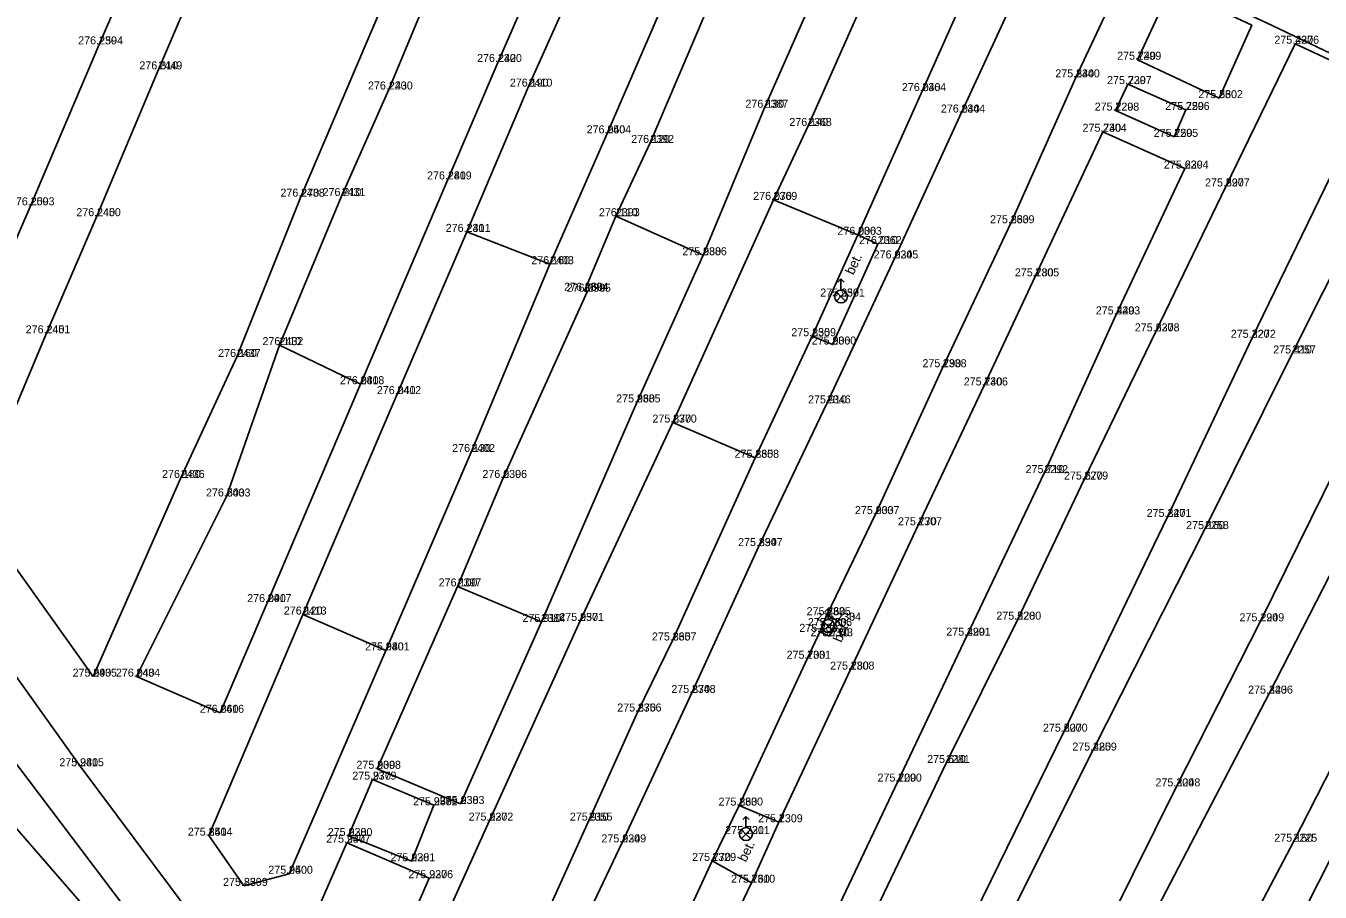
# Model space of a CAD drawing. Extents: x -776701 to -776081, y -974398 to -973771.
# Drawn here: x -776453.14 to -776412.71, y -974160.9 to -974133.83 of the extents above; entities that cross this region are included whole.
import ezdxf

# ---------------------------------------------------------------- set-up
doc = ezdxf.new("R2010")
doc.units = 0
for name, color, linetype in [('1 Body-bod', 7, 'Continuous'), ('10 Silnice-chodniky', 7, 'Continuous'), ('2 Body-cislo', 7, 'Continuous'), ('3 Body-vyska', 7, 'Continuous'), ('40 Popis-povrch', 7, 'Continuous'), ('58 Mobiliar', 7, 'Continuous'), ('7 Ploty', 7, 'Continuous'), ('Hranice parcel', 7, 'Continuous')]:
    doc.layers.add(name, color=color, linetype=linetype)

msp = doc.modelspace()

# ---------------------------------------------------------------- linework, layer by layer
at = {"layer": '1 Body-bod'}
for p, q in [((-776450.85, -974134.41), (-776450.85, -974134.41)), ((-776413.49, -974134.39), (-776413.49, -974134.39)), ((-776418.42, -974134.89), (-776418.42, -974134.89)), ((-776449, -974135.19), (-776449, -974135.19)), ((-776438.39, -974134.96), (-776438.39, -974134.96)), ((-776437.44, -974135.73), (-776437.44, -974135.73)), ((-776420.34, -974135.44), (-776420.34, -974135.44)), ((-776418.72, -974135.65), (-776418.72, -974135.65)), ((-776441.8, -974135.82), (-776441.8, -974135.82)), ((-776425.14, -974135.87), (-776425.14, -974135.87)), ((-776415.87, -974136.09), (-776415.87, -974136.09)), ((-776430.07, -974136.39), (-776430.07, -974136.39)), ((-776419.11, -974136.48), (-776419.11, -974136.48)), ((-776416.91, -974136.46), (-776416.91, -974136.46)), ((-776423.92, -974136.54), (-776423.92, -974136.54)), ((-776434.98, -974137.19), (-776434.98, -974137.19)), ((-776428.71, -974136.96), (-776428.71, -974136.96)), ((-776419.5, -974137.14), (-776419.5, -974137.14)), ((-776417.27, -974137.3), (-776417.27, -974137.3)), ((-776433.64, -974137.49), (-776433.64, -974137.49)), ((-776416.94, -974138.29), (-776416.94, -974138.29)), ((-776439.96, -974138.63), (-776439.96, -974138.63)), ((-776415.66, -974138.85), (-776415.66, -974138.85)), ((-776444.55, -974139.17), (-776444.55, -974139.17)), ((-776443.28, -974139.15), (-776443.28, -974139.15)), ((-776429.79, -974139.27), (-776429.79, -974139.27)), ((-776452.99, -974139.44), (-776452.99, -974139.44)), ((-776450.92, -974139.78), (-776450.92, -974139.78)), ((-776434.71, -974139.78), (-776434.71, -974139.78)), ((-776422.38, -974140), (-776422.38, -974140)), ((-776439.37, -974140.27), (-776439.37, -974140.27)), ((-776427.15, -974140.36), (-776427.15, -974140.36)), ((-776426.53, -974140.65), (-776426.53, -974140.65)), ((-776436.77, -974141.28), (-776436.77, -974141.28)), ((-776431.99, -974141), (-776431.99, -974141)), ((-776426.01, -974141.1), (-776426.01, -974141.1)), ((-776421.61, -974141.66), (-776421.61, -974141.66)), ((-776435.69, -974142.11), (-776435.69, -974142.11)), ((-776435.61, -974142.14), (-776435.61, -974142.14)), ((-776427.68, -974142.29), (-776427.68, -974142.29)), ((-776419.08, -974142.85), (-776419.08, -974142.85)), ((-776417.85, -974143.38), (-776417.85, -974143.38)), ((-776452.5, -974143.44), (-776452.5, -974143.44)), ((-776445.22, -974143.81), (-776445.22, -974143.81)), ((-776428.58, -974143.53), (-776428.58, -974143.53)), ((-776427.95, -974143.79), (-776427.95, -974143.79)), ((-776414.84, -974143.58), (-776414.84, -974143.58)), ((-776446.55, -974144.18), (-776446.55, -974144.18)), ((-776413.59, -974144.07), (-776413.59, -974144.07)), ((-776424.5, -974144.5), (-776424.5, -974144.5)), ((-776442.69, -974145.03), (-776442.69, -974145.03)), ((-776441.54, -974145.34), (-776441.54, -974145.34)), ((-776423.21, -974145.07), (-776423.21, -974145.07)), ((-776434.06, -974145.6), (-776434.06, -974145.6)), ((-776428.12, -974145.63), (-776428.12, -974145.63)), ((-776432.93, -974146.23), (-776432.93, -974146.23)), ((-776439.23, -974147.15), (-776439.23, -974147.15)), ((-776430.36, -974147.33), (-776430.36, -974147.33)), ((-776421.33, -974147.81), (-776421.33, -974147.81)), ((-776448.3, -974147.96), (-776448.3, -974147.96)), ((-776438.23, -974147.96), (-776438.23, -974147.96)), ((-776420.08, -974148.01), (-776420.08, -974148.01)), ((-776446.87, -974148.54), (-776446.87, -974148.54)), ((-776426.6, -974149.09), (-776426.6, -974149.09)), ((-776425.27, -974149.44), (-776425.27, -974149.44)), ((-776417.48, -974149.18), (-776417.48, -974149.18)), ((-776416.31, -974149.56), (-776416.31, -974149.56)), ((-776430.25, -974150.09), (-776430.25, -974150.09)), ((-776439.66, -974151.35), (-776439.66, -974151.35)), ((-776445.59, -974151.84), (-776445.59, -974151.84)), ((-776444.49, -974152.23), (-776444.49, -974152.23)), ((-776428.12, -974152.25), (-776428.12, -974152.25)), ((-776437.04, -974152.46), (-776437.04, -974152.46)), ((-776435.83, -974152.43), (-776435.83, -974152.43)), ((-776428.08, -974152.59), (-776428.08, -974152.59)), ((-776427.8, -974152.42), (-776427.8, -974152.42)), ((-776422.17, -974152.39), (-776422.17, -974152.39)), ((-776414.58, -974152.44), (-776414.58, -974152.44)), ((-776432.94, -974153.04), (-776432.94, -974153.04)), ((-776428.34, -974152.77), (-776428.34, -974152.77)), ((-776428.05, -974152.91), (-776428.05, -974152.91)), ((-776423.75, -974152.89), (-776423.75, -974152.89)), ((-776441.9, -974153.35), (-776441.9, -974153.35)), ((-776428.74, -974153.61), (-776428.74, -974153.61)), ((-776451.04, -974154.17), (-776451.04, -974154.17)), ((-776449.69, -974154.17), (-776449.69, -974154.17)), ((-776427.38, -974153.95), (-776427.38, -974153.95)), ((-776432.34, -974154.68), (-776432.34, -974154.68)), ((-776414.31, -974154.7), (-776414.31, -974154.7)), ((-776447.07, -974155.3), (-776447.07, -974155.3)), ((-776434.03, -974155.26), (-776434.03, -974155.26)), ((-776420.72, -974155.89), (-776420.72, -974155.89)), ((-776419.81, -974156.48), (-776419.81, -974156.48)), ((-776451.45, -974156.97), (-776451.45, -974156.97)), ((-776442.17, -974157.05), (-776442.17, -974157.05)), ((-776424.4, -974156.87), (-776424.4, -974156.87)), ((-776442.31, -974157.39), (-776442.31, -974157.39)), ((-776425.9, -974157.45), (-776425.9, -974157.45)), ((-776417.2, -974157.6), (-776417.2, -974157.6)), ((-776440.4, -974158.19), (-776440.4, -974158.19)), ((-776439.56, -974158.15), (-776439.56, -974158.15)), ((-776430.86, -974158.2), (-776430.86, -974158.2)), ((-776438.66, -974158.67), (-776438.66, -974158.67)), ((-776435.56, -974158.67), (-776435.56, -974158.67)), ((-776429.62, -974158.72), (-776429.62, -974158.72)), ((-776447.43, -974159.14), (-776447.43, -974159.14)), ((-776443.06, -974159.15), (-776443.06, -974159.15)), ((-776430.65, -974159.09), (-776430.65, -974159.09)), ((-776443.12, -974159.36), (-776443.12, -974159.36)), ((-776434.51, -974159.35), (-776434.51, -974159.35)), ((-776413.55, -974159.33), (-776413.55, -974159.33)), ((-776441.1, -974159.94), (-776441.1, -974159.94)), ((-776431.7, -974159.93), (-776431.7, -974159.93)), ((-776444.92, -974160.33), (-776444.92, -974160.33)), ((-776446.33, -974160.71), (-776446.33, -974160.71)), ((-776440.54, -974160.47), (-776440.54, -974160.47)), ((-776430.48, -974160.61), (-776430.48, -974160.61))]:
    msp.add_line(p, q, dxfattribs=at)
at = {"layer": '10 Silnice-chodniky'}
for points in [[(-776398.71, -974141.07), (-776402.53, -974139.28), (-776406.41, -974137.48), (-776410.27, -974135.71), (-776414.21, -974133.82), (-776417.97, -974132.05), (-776421.8, -974130.27), (-776425.67, -974128.29), (-776429.7, -974126.41), (-776433.28, -974124.7), (-776436.96, -974123), (-776442.03, -974120.71), (-776442.3, -974120.97)], [(-776428.58, -974143.53), (-776427.95, -974143.79), (-776426.53, -974140.65), (-776427.15, -974140.36)], [(-776428.34, -974152.77), (-776428.05, -974152.91), (-776427.8, -974152.42), (-776428.12, -974152.25)], [(-776429.62, -974158.72), (-776430.86, -974158.2)], [(-776430.48, -974160.61), (-776431.7, -974159.93)]]:
    msp.add_lwpolyline(points, dxfattribs=at)
at = {"layer": '58 Mobiliar'}
for p, q in [((-776427.68, -974141.74), (-776427.78, -974141.84)), ((-776427.68, -974142.089), (-776427.68, -974141.74)), ((-776427.68, -974141.74), (-776427.58, -974141.84)), ((-776427.68, -974142.29), (-776427.823, -974142.147)), ((-776427.68, -974142.29), (-776427.537, -974142.147)), ((-776427.68, -974142.29), (-776427.823, -974142.432)), ((-776427.68, -974142.29), (-776427.68, -974142.29)), ((-776427.68, -974142.29), (-776427.537, -974142.432)), ((-776428.08, -974152.04), (-776428.18, -974152.14)), ((-776428.08, -974152.389), (-776428.08, -974152.04)), ((-776428.08, -974152.04), (-776427.98, -974152.14)), ((-776428.08, -974152.59), (-776428.223, -974152.448)), ((-776428.08, -974152.59), (-776428.223, -974152.733)), ((-776428.08, -974152.59), (-776427.938, -974152.448)), ((-776428.08, -974152.59), (-776428.08, -974152.59)), ((-776428.08, -974152.59), (-776427.938, -974152.733)), ((-776430.65, -974158.54), (-776430.75, -974158.64)), ((-776430.65, -974158.889), (-776430.65, -974158.54)), ((-776430.65, -974158.54), (-776430.55, -974158.64)), ((-776430.65, -974159.09), (-776430.792, -974158.948)), ((-776430.65, -974159.09), (-776430.792, -974159.233)), ((-776430.65, -974159.09), (-776430.508, -974158.948)), ((-776430.65, -974159.09), (-776430.65, -974159.09)), ((-776430.65, -974159.09), (-776430.508, -974159.233))]:
    msp.add_line(p, q, dxfattribs=at)
for centre in [(-776427.68, -974142.29), (-776428.08, -974152.59), (-776430.65, -974159.09)]:
    msp.add_circle(centre, 0.202, dxfattribs=at)
at = {"layer": '7 Ploty'}
for p, q in [((-776429.79, -974139.27), (-776427.15, -974140.36)), ((-776434.71, -974139.78), (-776431.99, -974141)), ((-776436.77, -974141.28), (-776439.37, -974140.27)), ((-776445.22, -974143.81), (-776442.69, -974145.03)), ((-776432.93, -974146.23), (-776430.36, -974147.33)), ((-776439.66, -974151.35), (-776437.04, -974152.46)), ((-776444.49, -974152.23), (-776441.9, -974153.35))]:
    msp.add_line(p, q, dxfattribs=at)
for points in [[(-776458.16, -974144.19), (-776455.54, -974145.34), (-776452.99, -974139.44), (-776450.85, -974134.41), (-776449.09, -974130.33), (-776447.86, -974127.46), (-776444.88, -974120.48), (-776446.452, -974119.83)], [(-776451.04, -974154.17), (-776448.3, -974147.96), (-776446.55, -974144.18), (-776444.55, -974139.17), (-776442.06, -974133.33), (-776440.04, -974128.66), (-776437.65, -974123.11), (-776442.3, -974120.97), (-776442.79, -974120.77), (-776444.79, -974125.39), (-776446.25, -974128.79), (-776447.25, -974131.1), (-776449, -974135.19), (-776450.92, -974139.78), (-776452.5, -974143.44), (-776454.8, -974148.9), (-776451.04, -974154.17)], [(-776447.07, -974155.3), (-776445.59, -974151.84), (-776442.69, -974145.03), (-776439.96, -974138.63), (-776438.39, -974134.96), (-776436.64, -974130.93), (-776436.36, -974131.01), (-776435.14, -974127.45), (-776433.99, -974124.76), (-776436.55, -974123.59), (-776437.8, -974126.49), (-776437.99, -974126.41), (-776439.28, -974129.76), (-776441.8, -974135.82), (-776443.28, -974139.15), (-776445.22, -974143.81), (-776446.87, -974148.54), (-776449.69, -974154.17), (-776447.07, -974155.3)], [(-776446.33, -974160.71), (-776444.92, -974160.33), (-776441.9, -974153.35), (-776439.23, -974147.15), (-776436.77, -974141.28), (-776434.98, -974137.19), (-776432.85, -974132.25), (-776430.38, -974126.5), (-776432.91, -974125.29), (-776435.46, -974131.3), (-776437.44, -974135.73), (-776439.37, -974140.27), (-776441.54, -974145.34), (-776444.49, -974152.23), (-776447.43, -974159.14), (-776446.33, -974160.71)], [(-776439.56, -974158.15), (-776437.04, -974152.46), (-776434.06, -974145.6), (-776431.99, -974141), (-776430.07, -974136.39), (-776426.49, -974128.27), (-776429.06, -974127.1), (-776431.68, -974132.88), (-776433.64, -974137.49), (-776434.71, -974139.78), (-776435.69, -974142.11), (-776435.61, -974142.14), (-776438.23, -974147.96), (-776439.66, -974151.35), (-776442.17, -974157.05), (-776439.56, -974158.15)], [(-776440.88, -974166.89), (-776439.33, -974166.93), (-776437.12, -974162.12), (-776435.56, -974158.67), (-776434.03, -974155.26), (-776432.94, -974153.04), (-776430.36, -974147.33), (-776428.58, -974143.53), (-776427.15, -974140.36), (-776425.14, -974135.87), (-776422.56, -974130.08), (-776425.14, -974128.92), (-776428.71, -974136.96), (-776429.79, -974139.27), (-776432.93, -974146.23), (-776435.83, -974152.43), (-776438.66, -974158.67), (-776441.87, -974165.77), (-776440.88, -974166.89)], [(-776435.48, -974167.97), (-776433.12, -974162.99), (-776431.7, -974159.93), (-776430.86, -974158.2), (-776428.74, -974153.61), (-776428.34, -974152.77), (-776428.12, -974152.25), (-776426.6, -974149.09), (-776424.5, -974144.5), (-776422.38, -974140), (-776420.34, -974135.44), (-776418.71, -974131.96), (-776421.25, -974130.77), (-776423.92, -974136.54), (-776426.01, -974141.1), (-776428.12, -974145.63), (-776430.25, -974150.09), (-776432.34, -974154.68), (-776434.51, -974159.35), (-776436.78, -974164.14), (-776438.04, -974166.77), (-776435.48, -974167.97)], [(-776418.42, -974134.89), (-776417.37, -974132.62), (-776414.85, -974133.81), (-776415.87, -974136.09), (-776418.42, -974134.89)], [(-776432.01, -974176.96), (-776430.15, -974174.43), (-776428.84, -974172.48), (-776426.21, -974167.13), (-776424.02, -974162.64), (-776420.72, -974155.89), (-776417.48, -974149.18), (-776414.84, -974143.58), (-776412.06, -974137.85), (-776410.96, -974135.57), (-776413.49, -974134.39), (-776415.66, -974138.85), (-776417.85, -974143.38), (-776420.08, -974148.01), (-776422.17, -974152.39), (-776424.4, -974156.87), (-776426.57, -974161.43), (-776428.76, -974165.89), (-776429.88, -974168.2), (-776431.18, -974170.86), (-776433.91, -974174.88), (-776432.01, -974176.96)], [(-776417.27, -974137.3), (-776416.91, -974136.46), (-776418.72, -974135.65), (-776419.11, -974136.48), (-776417.27, -974137.3)], [(-776431.34, -974177.69), (-776430.36, -974178.74), (-776429.05, -974179.3), (-776425.05, -974173.32), (-776421.66, -974166.59), (-776420.59, -974164.45), (-776417.2, -974157.6), (-776414.58, -974152.44), (-776411.04, -974145.26), (-776408.67, -974140.55), (-776407.14, -974137.4), (-776409.65, -974136.23), (-776410.76, -974138.44), (-776413.59, -974144.07), (-776416.31, -974149.56), (-776419.81, -974156.48), (-776423.16, -974163.16), (-776425.35, -974167.56), (-776426.48, -974169.85), (-776427.57, -974172.05), (-776429.18, -974174.63), (-776431.34, -974177.69)], [(-776431.15, -974168.39), (-776429.66, -974165.41), (-776428.19, -974162.28), (-776425.9, -974157.45), (-776423.75, -974152.89), (-776421.33, -974147.81), (-776419.08, -974142.85), (-776416.94, -974138.29), (-776419.5, -974137.14), (-776421.61, -974141.66), (-776423.21, -974145.07), (-776425.27, -974149.44), (-776427.38, -974153.95), (-776429.62, -974158.72), (-776430.48, -974160.61), (-776432.15, -974164.11), (-776433.43, -974166.78), (-776434.67, -974168.81), (-776435.8, -974170.57), (-776436.61, -974171.85), (-776435.2, -974173.42), (-776434.19, -974173.45), (-776431.15, -974168.39)], [(-776418.01, -974168.03), (-776415.29, -974162.66), (-776413.55, -974159.33), (-776411.84, -974155.99), (-776409.48, -974151.54), (-776407.12, -974147.02), (-776405.49, -974143.66), (-776403.24, -974139.19), (-776405.79, -974138.02), (-776406.91, -974140.22), (-776409.14, -974144.68), (-776412.02, -974150.23), (-776414.31, -974154.7), (-776417.77, -974161.35), (-776420.5, -974166.71), (-776418.01, -974168.03)], [(-776415.33, -974192.73), (-776418.2, -974190.66), (-776421.23, -974188.49), (-776424.36, -974186.24), (-776427.39, -974184), (-776430.07, -974181.99), (-776432.38, -974179.43), (-776434.94, -974176.63), (-776434.87, -974176.53), (-776437.47, -974173.79), (-776440.34, -974170.82), (-776442.68, -974168.36), (-776445.15, -974165.67), (-776446.94, -974163.01), (-776451.45, -974156.97), (-776456.49, -974149.91), (-776458.27, -974147.5), (-776460.71, -974144.17), (-776461.87, -974145.07)], [(-776442.31, -974157.39), (-776443.06, -974159.15), (-776441.1, -974159.94), (-776440.4, -974158.19), (-776442.31, -974157.39)], [(-776443.53, -974163.89), (-776441.99, -974163.81), (-776440.54, -974160.47), (-776443.12, -974159.36), (-776444.56, -974162.68), (-776443.53, -974163.89)], [(-776412.09, -974159.27), (-776414.44, -974163.91), (-776416.71, -974168.32), (-776417.85, -974170.49), (-776419.07, -974172.75), (-776416.58, -974174.05)]]:
    msp.add_lwpolyline(points, dxfattribs=at)
at = {"layer": 'Hranice parcel'}
for p in [(-776493.37, -974104.35), (-776461.03, -974150.2)]:
    msp.add_line(p, (-776441.53, -974172.59), dxfattribs=at)

# ---------------------------------------------------------------- texts
at = {"layer": '2 Body-cislo'}
for s, p in [('2594', (-776450.85, -974134.41)), ('2276', (-776413.49, -974134.39)), ('2420', (-776438.39, -974134.96)), ('2299', (-776418.42, -974134.89)), ('2449', (-776449, -974135.19)), ('2340', (-776420.34, -974135.44)), ('2430', (-776441.8, -974135.82)), ('2410', (-776437.44, -974135.73)), ('2364', (-776425.14, -974135.87)), ('2297', (-776418.72, -974135.65)), ('2302', (-776415.87, -974136.09)), ('2387', (-776430.07, -974136.39)), ('2344', (-776423.92, -974136.54)), ('2298', (-776419.11, -974136.48)), ('2296', (-776416.91, -974136.46)), ('2404', (-776434.98, -974137.19)), ('2368', (-776428.71, -974136.96)), ('2304', (-776419.5, -974137.14)), ('2392', (-776433.64, -974137.49)), ('2295', (-776417.27, -974137.3)), ('2294', (-776416.94, -974138.29)), ('2419', (-776439.96, -974138.63)), ('2438', (-776444.55, -974139.17)), ('2431', (-776443.28, -974139.15)), ('2277', (-776415.66, -974138.85)), ('2593', (-776452.99, -974139.44)), ('2369', (-776429.79, -974139.27)), ('2450', (-776450.92, -974139.78)), ('2393', (-776434.71, -974139.78)), ('2339', (-776422.38, -974140)), ('2411', (-776439.37, -974140.27)), ('2363', (-776427.15, -974140.36)), ('2362', (-776426.53, -974140.65)), ('2386', (-776431.99, -974141)), ('2345', (-776426.01, -974141.1)), ('2403', (-776436.77, -974141.28)), ('2305', (-776421.61, -974141.66)), ('2394', (-776435.69, -974142.11)), ('2395', (-776435.61, -974142.14)), ('2361', (-776427.68, -974142.29)), ('2293', (-776419.08, -974142.85)), ('2451', (-776452.5, -974143.44)), ('2359', (-776428.58, -974143.53)), ('2278', (-776417.85, -974143.38)), ('2272', (-776414.84, -974143.58)), ('2432', (-776445.22, -974143.81)), ('2360', (-776427.95, -974143.79)), ('2257', (-776413.59, -974144.07)), ('2437', (-776446.55, -974144.18)), ('2338', (-776424.5, -974144.5)), ('2418', (-776442.69, -974145.03)), ('2306', (-776423.21, -974145.07)), ('2412', (-776441.54, -974145.34)), ('2385', (-776434.06, -974145.6)), ('2346', (-776428.12, -974145.63)), ('2370', (-776432.93, -974146.23)), ('2402', (-776439.23, -974147.15)), ('2358', (-776430.36, -974147.33)), ('2436', (-776448.3, -974147.96)), ('2396', (-776438.23, -974147.96)), ('2292', (-776421.33, -974147.81)), ('2279', (-776420.08, -974148.01)), ('2433', (-776446.87, -974148.54)), ('2337', (-776426.6, -974149.09)), ('2271', (-776417.48, -974149.18)), ('2307', (-776425.27, -974149.44)), ('2258', (-776416.31, -974149.56)), ('2347', (-776430.25, -974150.09)), ('2397', (-776439.66, -974151.35)), ('2417', (-776445.59, -974151.84)), ('2413', (-776444.49, -974152.23)), ('2384', (-776437.04, -974152.46)), ('2371', (-776435.83, -974152.43)), ('2335', (-776428.12, -974152.25)), ('2334', (-776427.8, -974152.42)), ('2280', (-776422.17, -974152.39)), ('2249', (-776414.58, -974152.44)), ('2332', (-776428.34, -974152.77)), ('2336', (-776428.08, -974152.59)), ('2333', (-776428.05, -974152.91)), ('2291', (-776423.75, -974152.89)), ('2401', (-776441.9, -974153.35)), ('2357', (-776432.94, -974153.04)), ('2331', (-776428.74, -974153.61)), ('2435', (-776451.04, -974154.17)), ('2434', (-776449.69, -974154.17)), ('2308', (-776427.38, -974153.95)), ('2348', (-776432.34, -974154.68)), ('2236', (-776414.31, -974154.7)), ('2416', (-776447.07, -974155.3)), ('2356', (-776434.03, -974155.26)), ('2270', (-776420.72, -974155.89)), ('2259', (-776419.81, -974156.48)), ('2415', (-776451.45, -974156.97)), ('2281', (-776424.4, -974156.87)), ('2379', (-776442.31, -974157.39)), ('2398', (-776442.17, -974157.05)), ('2290', (-776425.9, -974157.45)), ('2248', (-776417.2, -974157.6)), ('2382', (-776440.4, -974158.19)), ('2383', (-776439.56, -974158.15)), ('2330', (-776430.86, -974158.2)), ('2372', (-776438.66, -974158.67)), ('2355', (-776435.56, -974158.67)), ('2309', (-776429.62, -974158.72)), ('2414', (-776447.43, -974159.14)), ('2377', (-776443.12, -974159.36)), ('2380', (-776443.06, -974159.15)), ('2349', (-776434.51, -974159.35)), ('2311', (-776430.65, -974159.09)), ('2225', (-776413.55, -974159.33)), ('2381', (-776441.1, -974159.94)), ('2329', (-776431.7, -974159.93)), ('2400', (-776444.92, -974160.33)), ('2376', (-776440.54, -974160.47)), ('2310', (-776430.48, -974160.61)), ('2399', (-776446.33, -974160.71))]:
    msp.add_text(s, height=0.25, dxfattribs=at).set_placement(p)
at = {"layer": '3 Body-vyska'}
for s, p in [('276.230', (-776451.507, -974134.41)), ('275.430', (-776414.143, -974134.39)), ('276.230', (-776439.047, -974134.96)), ('275.740', (-776419.055, -974134.89)), ('276.310', (-776449.595, -974135.19)), ('275.840', (-776420.985, -974135.44)), ('276.220', (-776442.455, -974135.82)), ('276.190', (-776438.023, -974135.73)), ('276.040', (-776425.778, -974135.87)), ('275.730', (-776419.368, -974135.65)), ('275.560', (-776416.518, -974136.09)), ('276.130', (-776430.665, -974136.39)), ('276.040', (-776424.558, -974136.54)), ('275.720', (-776419.756, -974136.48)), ('275.750', (-776417.552, -974136.46)), ('276.050', (-776435.625, -974137.19)), ('276.140', (-776429.293, -974136.96)), ('275.740', (-776420.135, -974137.14)), ('276.120', (-776434.233, -974137.49)), ('275.750', (-776417.912, -974137.3)), ('275.630', (-776417.593, -974138.29)), ('276.280', (-776440.609, -974138.63)), ('276.270', (-776445.189, -974139.17)), ('276.210', (-776443.873, -974139.15)), ('275.590', (-776416.308, -974138.85)), ('276.200', (-776453.639, -974139.44)), ('276.070', (-776430.422, -974139.27)), ('276.240', (-776451.565, -974139.78)), ('276.110', (-776435.241, -974139.78)), ('275.860', (-776423.025, -974140)), ('276.230', (-776440.027, -974140.27)), ('276.000', (-776427.792, -974140.36)), ('276.010', (-776427.117, -974140.65)), ('275.980', (-776432.635, -974141)), ('276.020', (-776426.659, -974141.1)), ('276.160', (-776437.353, -974141.28)), ('275.780', (-776422.249, -974141.66)), ('276.060', (-776436.328, -974142.11)), ('276.090', (-776436.248, -974142.14)), ('275.950', (-776428.328, -974142.29)), ('275.440', (-776419.721, -974142.85)), ('276.240', (-776453.145, -974143.44)), ('275.850', (-776429.232, -974143.53)), ('275.630', (-776418.503, -974143.38)), ('275.320', (-776415.504, -974143.58)), ('276.110', (-776445.751, -974143.81)), ('275.900', (-776428.595, -974143.79)), ('275.410', (-776414.179, -974144.07)), ('276.160', (-776447.133, -974144.18)), ('275.790', (-776425.135, -974144.5)), ('276.080', (-776443.332, -974145.03)), ('275.740', (-776423.845, -974145.07)), ('276.040', (-776442.178, -974145.34)), ('275.960', (-776434.701, -974145.6)), ('275.910', (-776428.709, -974145.63)), ('275.870', (-776433.569, -974146.23)), ('276.130', (-776439.825, -974147.15)), ('275.860', (-776431.005, -974147.33)), ('276.180', (-776448.887, -974147.96)), ('276.030', (-776438.881, -974147.96)), ('275.710', (-776421.914, -974147.81)), ('275.670', (-776420.715, -974148.01)), ('276.500', (-776447.515, -974148.54)), ('275.900', (-776427.245, -974149.09)), ('275.340', (-776418.133, -974149.18)), ('275.770', (-776425.899, -974149.44)), ('275.160', (-776416.899, -974149.56)), ('275.890', (-776430.895, -974150.09)), ('276.100', (-776440.247, -974151.35)), ('276.090', (-776446.228, -974151.84)), ('276.120', (-776445.083, -974152.23)), ('275.910', (-776437.629, -974152.46)), ('275.950', (-776436.478, -974152.43)), ('275.760', (-776428.755, -974152.25)), ('275.730', (-776428.448, -974152.42)), ('275.520', (-776422.828, -974152.39)), ('275.290', (-776415.232, -974152.44)), ('275.750', (-776428.982, -974152.77)), ('275.760', (-776428.715, -974152.59)), ('275.710', (-776428.634, -974152.91)), ('275.490', (-776424.391, -974152.89)), ('275.980', (-776442.545, -974153.35)), ('275.860', (-776433.585, -974153.04)), ('275.700', (-776429.379, -974153.61)), ('275.990', (-776451.681, -974154.17)), ('276.040', (-776450.328, -974154.17)), ('275.780', (-776428.019, -974153.95)), ('275.870', (-776432.979, -974154.68)), ('275.340', (-776414.963, -974154.7)), ('276.060', (-776447.708, -974155.3)), ('275.870', (-776434.669, -974155.26)), ('275.500', (-776421.372, -974155.89)), ('275.480', (-776420.455, -974156.48)), ('275.980', (-776452.095, -974156.97)), ('275.610', (-776424.989, -974156.87)), ('275.970', (-776442.945, -974157.39)), ('275.900', (-776442.815, -974157.05)), ('275.700', (-776426.539, -974157.45)), ('275.300', (-776417.857, -974157.6)), ('275.950', (-776441.048, -974158.19)), ('275.930', (-776440.213, -974158.15)), ('275.860', (-776431.505, -974158.2)), ('275.920', (-776439.312, -974158.67)), ('275.910', (-776436.149, -974158.67)), ('275.730', (-776430.268, -974158.72)), ('275.850', (-776448.082, -974159.14)), ('275.940', (-776443.761, -974159.36)), ('275.920', (-776443.712, -974159.15)), ('275.920', (-776435.162, -974159.35)), ('275.720', (-776431.296, -974159.09)), ('275.150', (-776414.146, -974159.33)), ('275.920', (-776441.752, -974159.94)), ('275.770', (-776432.329, -974159.93)), ('275.950', (-776445.568, -974160.33)), ('275.920', (-776441.192, -974160.47)), ('275.760', (-776431.115, -974160.61)), ('275.850', (-776446.982, -974160.71))]:
    msp.add_text(s, height=0.25, dxfattribs=at).set_placement(p)
at = {"layer": '40 Popis-povrch'}
for rotation, p in [(65.6661, (-776427.29, -974141.635)), (67.0679, (-776427.667, -974153.122)), (64.1011, (-776430.65, -974159.987))]:
    msp.add_text('bet.', height=0.3, rotation=rotation, dxfattribs=at).set_placement(p)

doc.saveas('drawing.dxf')
